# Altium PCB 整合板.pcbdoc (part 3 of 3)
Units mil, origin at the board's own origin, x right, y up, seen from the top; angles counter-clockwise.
Board outline 5095 x 5568.76 mil, 2 copper layers (Top Layer, Bottom Layer); 124 components, 78 nets, 425 pads, 497 vias.
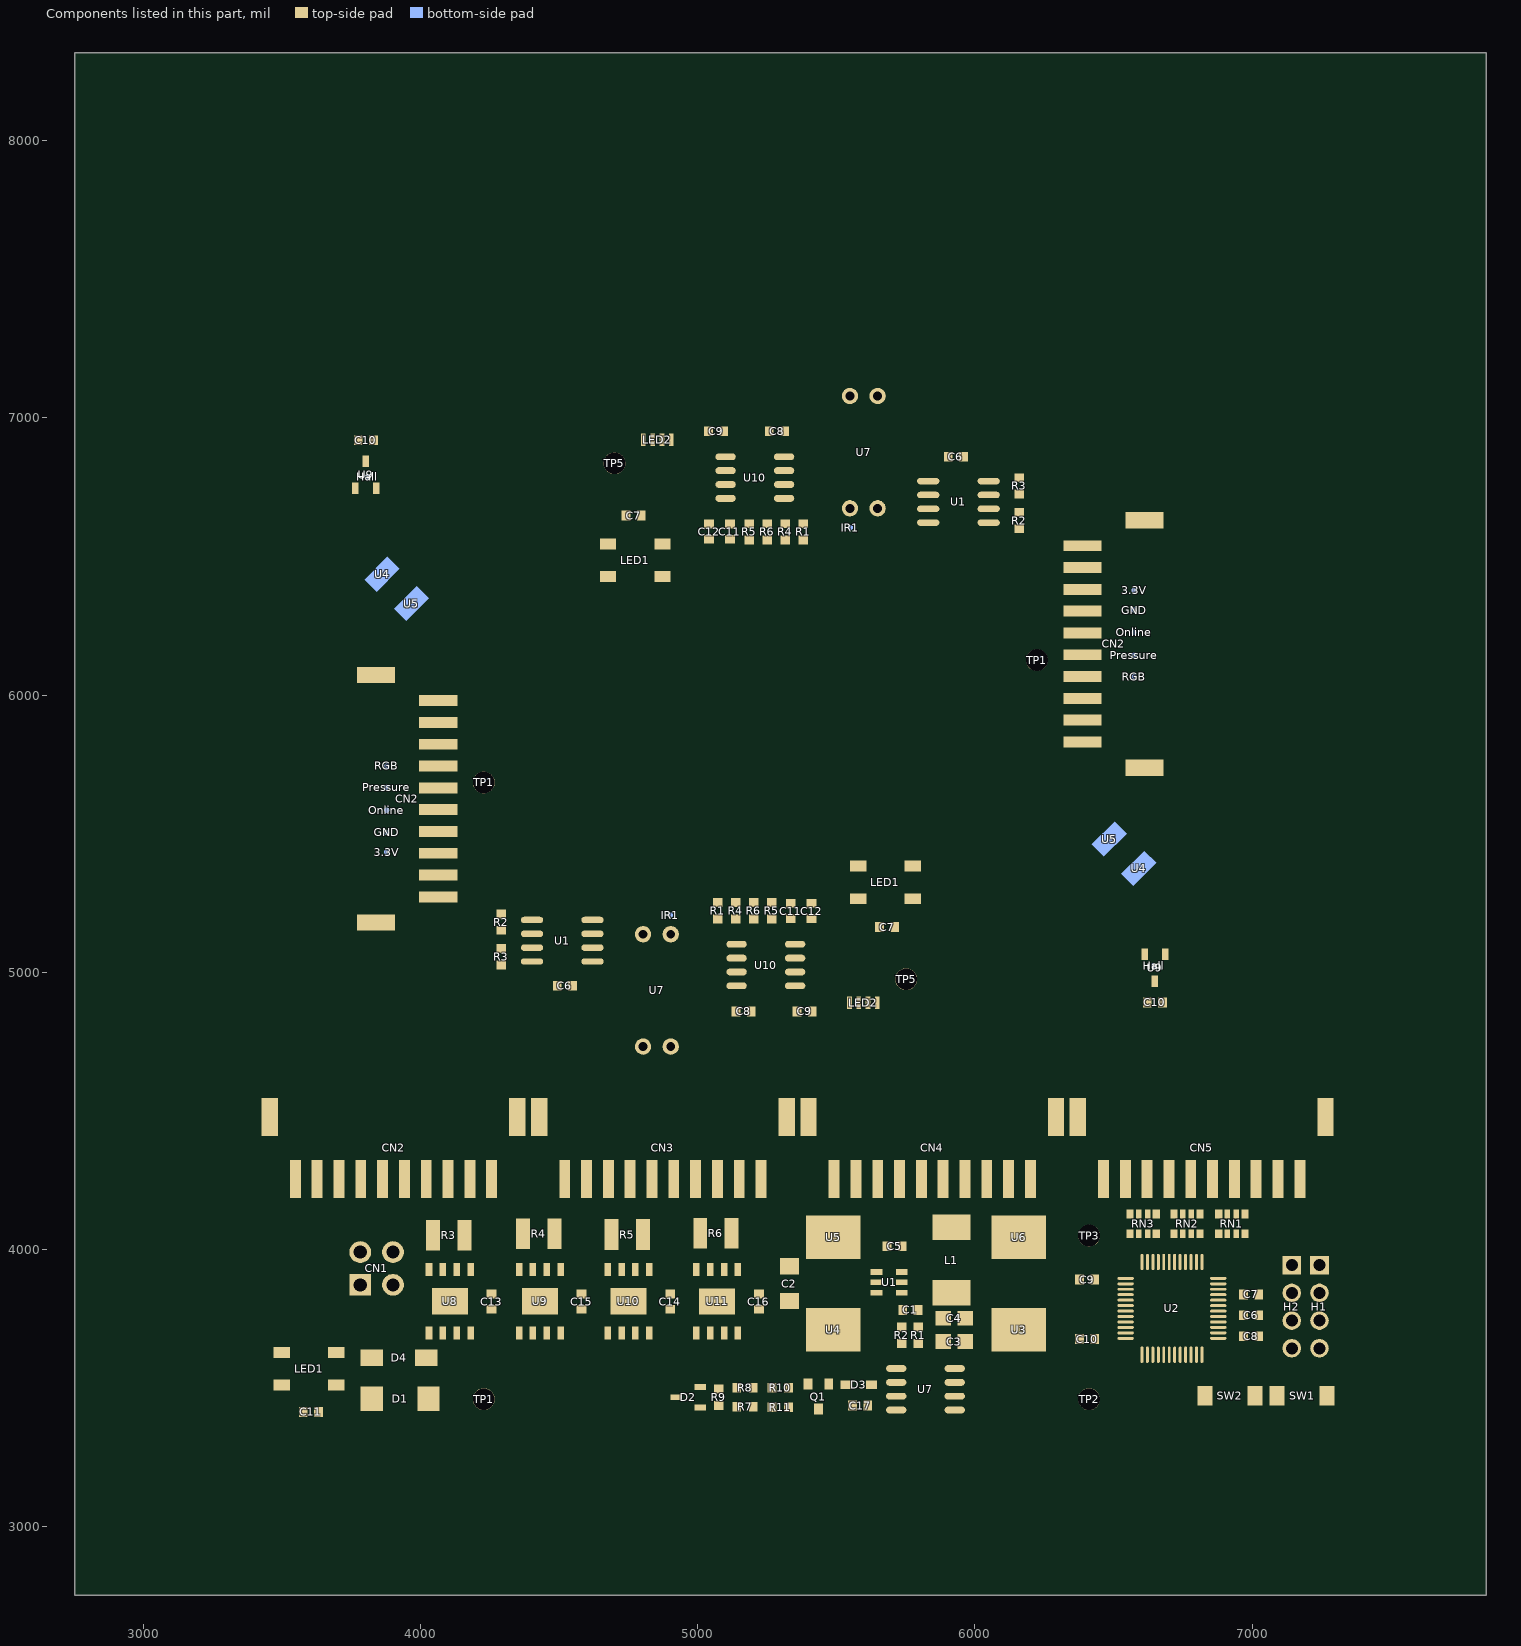
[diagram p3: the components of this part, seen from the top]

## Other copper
Top Layer:
  region net $1N2756: 5726.15,3914.4 5726.15,4010.05 5745.45,4010.05 5745.45,3914.4
  region net GND: 5621.51,3601.33 5621.51,3677.02 5674.82,3677.02 5674.82,3601.33
  region net GND: 5863.84,3606.42 5863.84,3676.62 5907.28,3676.62 5907.28,3606.42
  region net $1N6554: 5735.96,3709.21 5800.02,3709.21 5800.02,3725.45 5735.96,3725.45
  region net GND: 5675.21,3822.4 5675.21,3855 5705,3855 5705,3675.27 5753.05,3675.27 5753.05,3643.37 5597.4,3643.37 5597.4,3822.4
  region net 3.3V: 5919.34,3698.75 5919.34,3639.78 6064.27,3639.78 6064.27,3717.34 5930.5,3717.34 5930.5,3888.24 5829.77,3888.24 5829.77,3698.75
  region net $1N6554: 5727.77,3712.65 5727.77,3841.35 5743.86,3841.35 5743.86,3712.65
  region net 24V: 5444.66,3740.08 5444.66,3863.97 5585.94,3863.97 5585.94,3853.49 5665.87,3853.49 5665.87,3832.17 5586.02,3832.17 5586.02,3740.08
  region net GND: 6047.32,3724.17 6047.32,3798.86 6173.77,3798.86 6173.77,3952.87 6175.74,3952.87 6175.74,4127.93 5997.39,4127.93 5997.39,3775.88 5954.38,3775.88 5954.38,3724.17
  region net GND: 5443.72,3886.16 5443.72,3998.7 5586.67,3998.7 5586.67,3928.01 5666.01,3928.01 5666.01,3907.15 5586.75,3907.15 5586.75,3886.74 5532.46,3886.74 5532.46,3886.16
  region net $1N2752: 5623.59,3869.71 5623.59,3890.18 5673.61,3890.18 5673.61,4101.77 5861.12,4101.77 5861.12,4058.56 5702.51,4058.56 5702.51,3869.71
  region net GND: 5554.86,3956.3 5660,3956.3 5660,4060 5554.86,4060

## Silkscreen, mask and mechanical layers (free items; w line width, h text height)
Top Silkscreen Layer:
  region: 5110.81,6894.93 ccw(c5100.31,6894.71) 5089.81,6894.93 ccw(c5100.31,6895.14)
  region: 5360.58,4915.31 ccw(c5350.07,4915.31) 5339.57,4915.31 ccw(c5350.07,4915.31)
  circle w10: c6025.03,3560.31 r39.69
  region: 4939.04,6342.03 4865.19,6342.03 4939.04,6411.36
  region: 5511.34,5468.21 5585.19,5468.21 5511.34,5398.87
  region: 4315,3360 4475,3520 4775,3520 4935,3360
  region: 3450,3662.74 3450,3705 3505.54,3705
  lines w10: 5468.61,3620.01 6177.27,3620.01 6177.27,4131.82 5468.61,4131.82 5468.61,3620.01 ; 6990,3540 6990,3655.32 7092.98,3655.32 7092.98,3540 6990,3540
  text "4" at 3470,4215 h80
  text "3" at 4442.44,4215 h80
  text "2" at 5414.88,4215 h80
  text "1" at 6387.32,4215 h80
  text "R T /  - +" at 7095,3550 h50 r90
  text "+" at 6094.23,3517.95 h140 r90
  text "B" at 6965,3355 h80 r90
  text "R" at 7225,3355 h80 r90
Bottom Silkscreen Layer:
  text "M2" at 4700.31,6734.93 h60 r270
  text "+ M -" at 3924.87,6567.43 h69 r225
  text "M2" at 6329.49,6259.88 h60 r270
  text "Online" at 6730.31,6204.93 h45
  text "Pressure" at 6730.31,6154.93 h45
  text "Pressure" at 3720.07,5655.31 h45 r180
  text "Online" at 3720.07,5605.31 h45 r180
  text "M2" at 4120.89,5550.35 h60 r90
  text "+ M -" at 6525.51,5242.8 h69 r45
  text "M2" at 5750.07,5075.31 h60 r90
Mech6:
  drawing of 470 lines, arcs and shapes, not listed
